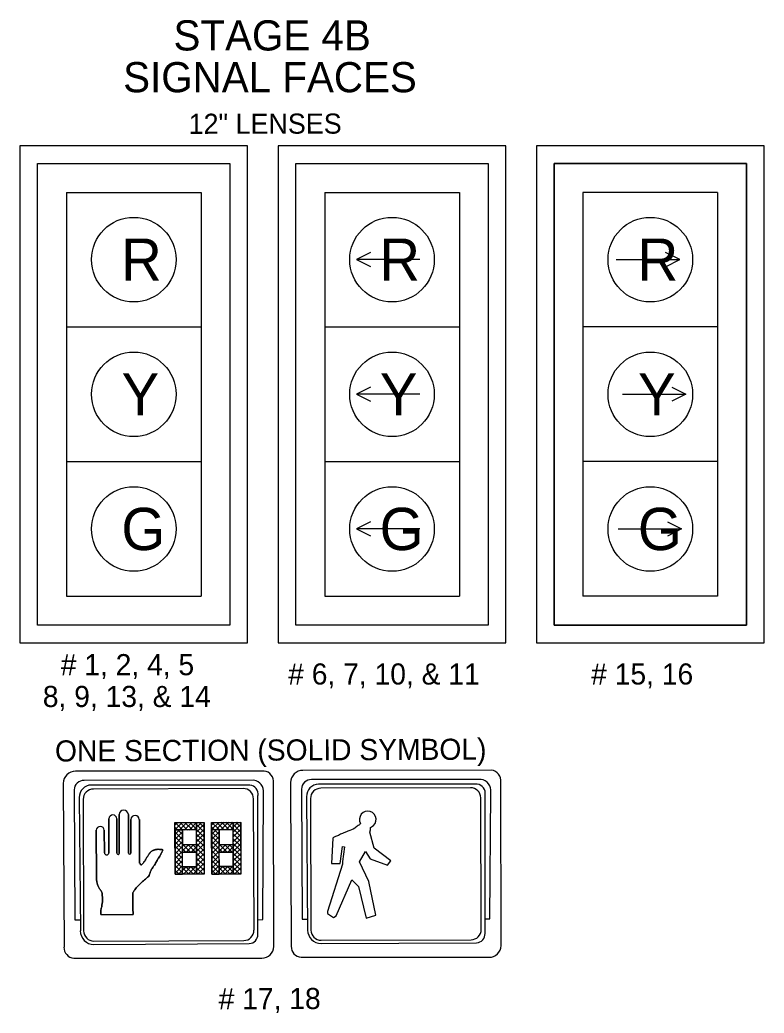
# Model space of a CAD drawing. Extents: x -218554 to 420030, y -565899 to -483460.
# Drawn here: x 418293.9 to 418442, y -565493.6 to -565296.1 of the extents above; entities that cross this region are included whole.
import ezdxf

# ---------------------------------------------------------------- set-up
doc = ezdxf.new("R2010")
doc.units = 0
for name, color, linetype in [('G-ANNO-STMP', 7, 'Continuous'), ('G-Border-Paper', 7, 'Continuous'), ('Level 1', 7, 'Continuous'), ('Level 61', 7, 'Continuous')]:
    doc.layers.add(name, color=color, linetype=linetype)

msp = doc.modelspace()

# ---------------------------------------------------------------- linework, layer by layer
at = {"layer": 'G-Border-Paper'}
for points in [[(418293.92, -565321.11), (418293.92, -565419.92), (418339.23, -565419.92), (418339.23, -565321.11), (418293.92, -565321.11)], [(418345.29, -565321.11), (418345.29, -565419.92), (418390.6, -565419.92), (418390.6, -565321.11), (418345.29, -565321.11)], [(418396.66, -565321.11), (418396.66, -565419.92), (418441.96, -565419.92), (418441.96, -565321.11), (418396.66, -565321.11)], [(418297.46, -565416.41), (418297.46, -565324.61), (418335.71, -565324.61), (418335.71, -565416.41), (418297.46, -565416.41)], [(418348.82, -565416.41), (418348.82, -565324.61), (418387.08, -565324.61), (418387.08, -565416.41), (418348.82, -565416.41)], [(418400.19, -565416.41), (418400.19, -565324.61), (418438.45, -565324.61), (418438.45, -565416.41), (418400.19, -565416.41)]]:
    msp.add_lwpolyline(points, dxfattribs=at)
at = {"layer": 'Level 1'}
for p, q in [((418342.52, -565445.42), (418305.02, -565445.45)), ((418387.72, -565445.26), (418350.22, -565445.29)), ((418302.57, -565447.88), (418302.71, -565480.42)), ((418340.45, -565447.24), (418306.73, -565447.28)), ((418339.68, -565448.2), (418308.13, -565448.2)), ((418344.42, -565480.3), (418344.39, -565447.79)), ((418347.77, -565447.72), (418347.91, -565480.26)), ((418385.66, -565447.08), (418351.94, -565447.12)), ((418384.89, -565448.04), (418353.34, -565448.05)), ((418389.63, -565480.14), (418389.59, -565447.63)), ((418386.46, -565477.72), (418386.5, -565450.16)), ((418305.73, -565450.68), (418305.96, -565477.2)), ((418341.26, -565477.88), (418341.29, -565450.31)), ((418350.94, -565450.52), (418351.16, -565477.04)), ((418313.7, -565461.8), (418313.67, -565454.08)), ((418313.67, -565454.08), (418313.7, -565461.8)), ((418315.51, -565454.05), (418315.54, -565461.72)), ((418315.54, -565461.72), (418315.51, -565454.05)), ((418311.64, -565461.66), (418311.62, -565454.91)), ((418311.62, -565454.91), (418311.64, -565461.66)), ((418313.22, -565454.92), (418313.24, -565461.76)), ((418313.24, -565461.76), (418313.22, -565454.92)), ((418316, -565461.75), (418315.97, -565455.03)), ((418315.97, -565455.03), (418316, -565461.75)), ((418317.69, -565455.07), (418317.72, -565463.73)), ((418317.72, -565463.73), (418317.69, -565455.07)), ((418324.77, -565456.14), (418325.25, -565455.65)), ((418324.78, -565457.09), (418326.21, -565455.65)), ((418324.78, -565458.05), (418327.16, -565455.65)), ((418324.83, -565455.66), (418326.33, -565457.15)), ((418325.79, -565455.65), (418327.29, -565457.15)), ((418326.63, -565457.15), (418328.12, -565455.64)), ((418326.74, -565455.65), (418328.25, -565457.14)), ((418327.58, -565457.15), (418329.08, -565455.64)), ((418327.7, -565455.65), (418330.55, -565458.48)), ((418328.54, -565457.14), (418330.03, -565455.64)), ((418328.66, -565455.64), (418330.55, -565457.52)), ((418329.05, -565457.59), (418330.54, -565456.08)), ((418329.61, -565455.64), (418330.55, -565456.57)), ((418332.07, -565458.02), (418334.46, -565455.62)), ((418332.07, -565456.11), (418332.55, -565455.63)), ((418332.07, -565457.07), (418333.5, -565455.63)), ((418332.12, -565455.63), (418333.63, -565457.13)), ((418333.08, -565455.63), (418334.59, -565457.12)), ((418333.92, -565457.12), (418335.42, -565455.62)), ((418334.04, -565455.62), (418335.54, -565457.12)), ((418334.88, -565457.12), (418336.37, -565455.62)), ((418334.99, -565455.62), (418337.85, -565458.45)), ((418335.83, -565457.12), (418337.33, -565455.61)), ((418335.95, -565455.62), (418337.84, -565457.5)), ((418336.34, -565457.56), (418337.84, -565456.06)), ((418336.91, -565455.61), (418337.84, -565456.54)), ((418309.16, -565466.52), (418309.13, -565457.2)), ((418309.13, -565457.2), (418309.16, -565466.52)), ((418310.72, -565457.21), (418310.74, -565461.66)), ((418310.74, -565461.66), (418310.72, -565457.21)), ((418324.77, -565456.55), (418326.28, -565458.05)), ((418324.78, -565459.01), (418326.28, -565457.5)), ((418324.78, -565457.51), (418326.28, -565459.01)), ((418329.05, -565458.55), (418330.55, -565457.04)), ((418329.05, -565457.94), (418330.56, -565459.44)), ((418329.06, -565459.5), (418330.55, -565458)), ((418332.07, -565456.53), (418333.57, -565458.02)), ((418332.07, -565457.49), (418333.58, -565458.98)), ((418332.08, -565458.98), (418333.57, -565457.48)), ((418336.35, -565458.52), (418337.84, -565457.02)), ((418336.35, -565457.92), (418337.85, -565459.41)), ((418336.35, -565459.48), (418337.85, -565457.97)), ((418363.87, -565456.54), (418363.87, -565456.54)), ((418324.78, -565458.47), (418327.88, -565461.55)), ((418324.78, -565459.43), (418326.92, -565461.55)), ((418324.79, -565459.96), (418326.28, -565458.46)), ((418324.79, -565460.92), (418326.28, -565459.41)), ((418324.79, -565461.88), (418326.61, -565460.05)), ((418324.8, -565462.83), (418327.56, -565460.05)), ((418326.29, -565460.05), (418329.06, -565460.04)), ((418327.02, -565461.55), (418328.52, -565460.04)), ((418327.33, -565460.05), (418328.84, -565461.54)), ((418327.98, -565461.54), (418330.55, -565458.95)), ((418328.29, -565460.04), (418330.57, -565462.31)), ((418328.94, -565461.54), (418330.56, -565459.91)), ((418329.05, -565458.9), (418330.56, -565460.39)), ((418329.06, -565459.85), (418330.56, -565461.35)), ((418332.08, -565459.94), (418333.58, -565458.43)), ((418332.08, -565458.44), (418335.17, -565461.52)), ((418332.08, -565460.89), (418333.58, -565459.39)), ((418332.08, -565459.4), (418334.22, -565461.52)), ((418332.09, -565461.85), (418333.9, -565460.02)), ((418332.09, -565462.81), (418334.86, -565460.02)), ((418333.58, -565460.03), (418336.35, -565460.02)), ((418334.32, -565461.52), (418335.81, -565460.02)), ((418334.63, -565460.02), (418336.13, -565461.52)), ((418335.28, -565461.52), (418337.85, -565458.93)), ((418335.58, -565460.02), (418337.86, -565462.28)), ((418336.23, -565461.52), (418337.85, -565459.89)), ((418336.35, -565458.87), (418337.85, -565460.37)), ((418336.35, -565459.83), (418337.86, -565461.32)), ((418324.79, -565460.38), (418326.29, -565461.88)), ((418324.79, -565461.34), (418326.3, -565462.83)), ((418326.29, -565461.55), (418329.06, -565461.54)), ((418329.06, -565461.77), (418330.57, -565463.26)), ((418329.07, -565462.37), (418330.56, -565460.87)), ((418329.07, -565463.33), (418330.56, -565461.82)), ((418332.08, -565460.36), (418333.59, -565461.85)), ((418332.09, -565461.31), (418333.59, -565462.81)), ((418333.59, -565461.53), (418336.36, -565461.52)), ((418336.36, -565462.35), (418337.86, -565460.84)), ((418336.36, -565461.74), (418337.86, -565463.24)), ((418336.36, -565463.3), (418337.86, -565461.8)), ((418324.79, -565462.3), (418326.3, -565463.79)), ((418324.8, -565463.79), (418326.29, -565462.28)), ((418324.8, -565464.75), (418326.3, -565463.24)), ((418324.8, -565463.25), (418327.51, -565465.95)), ((418327.42, -565465.95), (418330.57, -565462.78)), ((418328.38, -565465.94), (418330.57, -565463.74)), ((418329.07, -565462.73), (418330.57, -565464.22)), ((418329.07, -565463.68), (418330.58, -565465.18)), ((418332.09, -565463.76), (418333.59, -565462.26)), ((418332.09, -565462.27), (418333.59, -565463.76)), ((418332.09, -565463.23), (418334.81, -565465.92)), ((418332.1, -565464.72), (418333.59, -565463.22)), ((418334.72, -565465.92), (418337.86, -565462.76)), ((418335.68, -565465.92), (418337.87, -565463.71)), ((418336.36, -565462.7), (418337.87, -565464.19)), ((418336.37, -565463.66), (418337.87, -565465.15)), ((418324.8, -565464.21), (418326.55, -565465.95)), ((418324.8, -565465.17), (418325.6, -565465.95)), ((418324.81, -565465.7), (418326.3, -565464.2)), ((418325.51, -565465.95), (418327, -565464.45)), ((418326.47, -565465.95), (418327.96, -565464.44)), ((418326.96, -565464.45), (418328.47, -565465.94)), ((418327.92, -565464.45), (418329.42, -565465.94)), ((418328.88, -565464.44), (418330.38, -565465.94)), ((418329.34, -565465.94), (418330.57, -565464.69)), ((418330.29, -565465.94), (418330.58, -565465.65)), ((418332.1, -565465.68), (418333.6, -565464.17)), ((418332.1, -565464.18), (418333.85, -565465.92)), ((418332.1, -565465.14), (418332.89, -565465.93)), ((418332.8, -565465.93), (418334.3, -565464.42)), ((418333.76, -565465.92), (418335.26, -565464.42)), ((418334.26, -565464.42), (418335.76, -565465.92)), ((418335.21, -565464.42), (418336.72, -565465.91)), ((418336.17, -565464.42), (418337.68, -565465.91)), ((418336.63, -565465.91), (418337.87, -565464.67)), ((418337.59, -565465.91), (418337.87, -565465.63)), ((418310.02, -565473.96), (418316.46, -565473.98)), ((418316.44, -565473.98), (418310.06, -565474)), ((418316.47, -565473.98), (418316.44, -565473.98)), ((418308.66, -565479.89), (418339.56, -565479.72)), ((418353.87, -565479.73), (418384.76, -565479.57)), ((418304.68, -565482.61), (418342.02, -565482.61)), ((418349.88, -565482.46), (418387.23, -565482.46))]:
    msp.add_line(p, q, dxfattribs=at)
for points in [[(418304.72, -565449.17), (418304.89, -565475.03), (418305.97, -565475.02)], [(418338.36, -565448.89), (418308.56, -565449)], [(418341.24, -565474.98), (418342.22, -565474.97), (418342.38, -565449.79)], [(418349.93, -565449.02), (418350.09, -565474.87), (418351.18, -565474.87)], [(418383.56, -565448.74), (418353.76, -565448.84)], [(418386.45, -565474.82), (418387.42, -565474.81), (418387.58, -565449.63)], [(418306.52, -565451.05), (418306.61, -565477.2)], [(418340.5, -565477.08), (418340.41, -565450.93)], [(418351.72, -565450.89), (418351.81, -565477.04)], [(418385.7, -565476.92), (418385.61, -565450.77)], [(418329.06, -565460.04), (418329.05, -565457.14), (418326.28, -565457.15), (418326.29, -565460.05)], [(418336.35, -565460.02), (418336.34, -565457.12), (418333.57, -565457.13), (418333.58, -565460.03)], [(418356.2, -565458.74), (418355.92, -565463.81), (418357.66, -565463.81), (418358.1, -565460.45), (418358.5, -565460.46), (418358.07, -565463.44), (418358.07, -565463.94), (418355.12, -565473.36), (418355.13, -565473.73), (418356.32, -565474.55), (418356.82, -565474.18), (418359.96, -565467.06), (418361.25, -565468.38), (418362.78, -565474.66), (418364.75, -565474.06), (418363.36, -565467.41), (418361.46, -565463.47), (418362.69, -565461.45), (418363.57, -565462.91), (418367.06, -565464.14), (418367.74, -565463.27), (418364.42, -565460.77), (418363.55, -565457.6), (418363.69, -565457.13), (418363.69, -565456.62), (418363.87, -565456.54)], [(418329.06, -565461.54), (418329.07, -565464.44), (418326.3, -565464.45), (418326.29, -565461.55)], [(418336.36, -565461.52), (418336.37, -565464.42), (418333.6, -565464.43), (418333.59, -565461.53)], [(418308.66, -565479.23), (418338.46, -565479.13)], [(418353.87, -565479.08), (418383.67, -565478.97)]]:
    msp.add_lwpolyline(points, dxfattribs=at)
for points in [[(418324.77, -565455.66), (418330.54, -565455.64), (418330.58, -565465.94), (418324.81, -565465.96)], [(418324.77, -565455.66), (418329.05, -565455.65), (418329.05, -565457.14), (418324.77, -565457.14)], [(418329.05, -565455.65), (418330.57, -565455.65), (418330.58, -565465.94), (418329.05, -565465.94)], [(418332.07, -565455.63), (418337.84, -565455.61), (418337.87, -565465.91), (418332.1, -565465.93)], [(418332.07, -565455.63), (418336.34, -565455.63), (418336.34, -565457.12), (418332.07, -565457.12)], [(418336.34, -565455.63), (418337.86, -565455.63), (418337.87, -565465.91), (418336.35, -565465.91)], [(418324.81, -565465.96), (418326.28, -565465.95), (418326.28, -565457.15), (418324.8, -565457.15)], [(418332.1, -565465.93), (418333.58, -565465.93), (418333.57, -565457.13), (418332.09, -565457.13)], [(418326.29, -565460.05), (418329.06, -565460.05), (418329.06, -565461.54), (418326.29, -565461.54)], [(418333.58, -565460.03), (418336.36, -565460.02), (418336.36, -565461.52), (418333.58, -565461.52)], [(418326.3, -565464.45), (418329.05, -565464.45), (418329.05, -565465.94), (418326.3, -565465.94)], [(418333.6, -565464.43), (418336.35, -565464.42), (418336.35, -565465.91), (418333.6, -565465.91)]]:
    msp.add_lwpolyline(points, close=True, dxfattribs=at)
for centre, radius, start, end in [((418305.01, -565447.89), 2.44, 89.8211, 179.8211), ((418342.26, -565447.54), 2.14, 353.227, 83.227), ((418350.22, -565447.73), 2.44, 89.8211, 179.8211), ((418387.47, -565447.38), 2.14, 353.227, 83.227), ((418306.67, -565449.23), 1.95, 88.3219, 178.3219), ((418308.17, -565450.64), 2.44, 90.9287, 180.9287), ((418339.43, -565450.06), 1.88, 352.2729, 82.2729), ((418340.14, -565449.48), 2.26, 351.9574, 81.9574), ((418351.88, -565449.07), 1.95, 88.3219, 178.3219), ((418353.38, -565450.48), 2.44, 90.9287, 180.9287), ((418384.63, -565449.9), 1.88, 352.2729, 82.2729), ((418385.34, -565449.32), 2.26, 351.9574, 81.9574), ((418308.56, -565451.04), 2.04, 90.1989, 180.1989), ((418338.36, -565450.94), 2.04, 0.1989, 90.1989), ((418353.77, -565450.88), 2.04, 90.1989, 180.1989), ((418383.57, -565450.78), 2.04, 0.1989, 90.1989), ((418314.59, -565454.12), 0.921, 4.0989, 177.4457), ((418314.59, -565454.12), 0.921, 4.0989, 177.4457), ((418363.12, -565455.05), 1.66, 296.6638, 209.0011), ((418312.42, -565454.96), 0.801, 2.8665, 176.2133), ((418312.42, -565454.96), 0.801, 2.8665, 176.2133), ((418316.83, -565455.1), 0.857, 1.6765, 175.0233), ((418316.83, -565455.1), 0.857, 1.6765, 175.0233), ((418309.92, -565457.25), 0.801, 2.8665, 176.2133), ((418309.92, -565457.25), 0.801, 2.8665, 176.2133), ((418311.19, -565461.66), 0.45, 180.1989, 0.1989), ((418311.19, -565461.66), 0.45, 180.1989, 0.1989), ((418313.47, -565461.78), 0.231, 175.6215, 355.6215), ((418313.47, -565461.78), 0.231, 175.6215, 355.6215), ((418315.76, -565461.73), 0.234, 175.0942, 355.0942), ((418315.76, -565461.73), 0.234, 175.0942, 355.0942), ((418308.65, -565477.19), 2.7, 180.1989, 270.1989), ((418308.65, -565477.19), 2.04, 180.1989, 270.1989), ((418338.45, -565477.08), 2.04, 270.1989, 0.1989), ((418353.86, -565477.03), 2.7, 180.1989, 270.1989), ((418353.86, -565477.03), 2.04, 180.1989, 270.1989), ((418383.66, -565476.93), 2.04, 270.1989, 0.1989), ((418384.69, -565477.79), 1.77, 272.3085, 2.3085), ((418339.49, -565477.95), 1.77, 272.3085, 2.3085), ((418304.79, -565480.53), 2.09, 176.9799, 266.9799), ((418342.07, -565480.26), 2.36, 268.9594, 358.9594), ((418350, -565480.37), 2.09, 176.9799, 266.9799), ((418387.27, -565480.1), 2.36, 268.9594, 358.9594)]:
    msp.add_arc(centre, radius, start, end, dxfattribs=at)
for points in [[(418361.66, -565455.86), (418361.47, -565456.13), (418361.21, -565456.27), (418360.89, -565456.5), (418360.53, -565456.77), (418359.19, -565457.38), (418358.55, -565457.66), (418357.93, -565457.9), (418357.09, -565458.3), (418356.69, -565458.45), (418356.2, -565458.74)], [(418317.71, -565463.73), (418317.77, -565463.74), (418317.86, -565463.92), (418317.97, -565464.05), (418318.04, -565464.07), (418318.15, -565464.05), (418318.22, -565463.96), (418318.42, -565463.74), (418318.57, -565463.56), (418318.66, -565463.43), (418318.75, -565463.32), (418318.9, -565463.12), (418318.99, -565462.94), (418319.12, -565462.7), (418319.21, -565462.57), (418319.36, -565462.32), (418319.54, -565462.1), (418319.67, -565461.88), (418319.82, -565461.66), (418319.95, -565461.5), (418320.15, -565461.33), (418320.4, -565461.23), (418320.53, -565461.17), (418320.73, -565461.1), (418320.9, -565461.04), (418321.17, -565460.99), (418321.39, -565460.99), (418321.68, -565460.99), (418321.94, -565461.01), (418322.25, -565461.05), (418322.34, -565461.1), (418322.36, -565461.16), (418322.23, -565461.45), (418322.14, -565461.6), (418322.06, -565461.76), (418321.97, -565461.94), (418321.92, -565462.05), (418321.75, -565462.34), (418321.48, -565462.74), (418321.13, -565463.38), (418320.69, -565464.11), (418320.34, -565464.62), (418320.14, -565464.95), (418319.97, -565465.26), (418319.87, -565465.51), (418319.81, -565465.64), (418319.62, -565466.17), (418319.31, -565466.55), (418319.07, -565466.81), (418318.71, -565467.08), (418318.49, -565467.24), (418317.92, -565467.81), (418317.41, -565468.3), (418317.08, -565468.63), (418316.8, -565469.01), (418316.66, -565469.18), (418316.54, -565469.41), (418316.4, -565469.63), (418316.41, -565470.12), (418316.38, -565470.56), (418316.39, -565470.96), (418316.41, -565471.49), (418316.41, -565471.99), (418316.41, -565472.81), (418316.44, -565473.47), (418316.46, -565473.71), (418316.46, -565473.89), (418316.46, -565473.98)], [(418316.46, -565473.98), (418316.46, -565473.89), (418316.46, -565473.71), (418316.44, -565473.47), (418316.41, -565472.81), (418316.41, -565471.99), (418316.41, -565471.49), (418316.39, -565470.96), (418316.38, -565470.56), (418316.41, -565470.12), (418316.4, -565469.63), (418316.54, -565469.41), (418316.66, -565469.18), (418316.8, -565469.01), (418317.08, -565468.63), (418317.41, -565468.3), (418317.92, -565467.81), (418318.49, -565467.24), (418318.71, -565467.08), (418319.07, -565466.81), (418319.31, -565466.55), (418319.62, -565466.17), (418319.81, -565465.64), (418319.87, -565465.51), (418319.97, -565465.26), (418320.14, -565464.95), (418320.34, -565464.62), (418320.69, -565464.11), (418321.13, -565463.38), (418321.48, -565462.74), (418321.75, -565462.34), (418321.92, -565462.05), (418321.97, -565461.94), (418322.06, -565461.76), (418322.14, -565461.6), (418322.23, -565461.45), (418322.36, -565461.16), (418322.34, -565461.1), (418322.25, -565461.05), (418321.94, -565461.01), (418321.68, -565460.99), (418321.39, -565460.99), (418321.17, -565460.99), (418320.9, -565461.04), (418320.73, -565461.1), (418320.53, -565461.17), (418320.4, -565461.23), (418320.15, -565461.33), (418319.95, -565461.5), (418319.82, -565461.66), (418319.67, -565461.88), (418319.54, -565462.1), (418319.36, -565462.32), (418319.21, -565462.57), (418319.12, -565462.7), (418318.99, -565462.94), (418318.9, -565463.12), (418318.75, -565463.32), (418318.66, -565463.43), (418318.57, -565463.56), (418318.42, -565463.74), (418318.22, -565463.96), (418318.15, -565464.05), (418318.04, -565464.07), (418317.97, -565464.05), (418317.86, -565463.92), (418317.77, -565463.74), (418317.71, -565463.73)], [(418310.02, -565473.96), (418310.02, -565473.61), (418310.04, -565473.01), (418310.21, -565472.39), (418310.3, -565471.68), (418310.37, -565471.28), (418310.36, -565470.51), (418310.29, -565469.87), (418310.23, -565469.54), (418309.89, -565468.98), (418309.54, -565468.43), (418309.34, -565467.97), (418309.25, -565467.48), (418309.18, -565467.11), (418309.18, -565466.87), (418309.16, -565466.52)], [(418309.16, -565466.52), (418309.18, -565466.87), (418309.18, -565467.11), (418309.25, -565467.48), (418309.34, -565467.97), (418309.54, -565468.43), (418309.89, -565468.98), (418310.23, -565469.54), (418310.29, -565469.87), (418310.36, -565470.51), (418310.37, -565471.28), (418310.3, -565471.68), (418310.21, -565472.39), (418310.04, -565473.01), (418310.02, -565473.61), (418310.02, -565473.96)]]:
    msp.add_spline(points, degree=3, dxfattribs=at)
at = {"layer": 'Level 61'}
for p, q in [((418303.19, -565330.35), (418329.97, -565330.35)), ((418303.19, -565330.35), (418303.19, -565357.12)), ((418329.97, -565330.35), (418329.97, -565357.12)), ((418354.56, -565330.35), (418381.34, -565330.35)), ((418354.56, -565330.35), (418354.56, -565357.12)), ((418381.34, -565330.35), (418381.34, -565357.12)), ((418432.71, -565330.35), (418405.93, -565330.35)), ((418405.93, -565330.35), (418405.93, -565357.12)), ((418432.71, -565330.35), (418432.71, -565357.12)), ((418373.5, -565343.7), (418360.88, -565343.7)), ((418412.55, -565343.73), (418425.17, -565343.73)), ((418303.19, -565357.12), (418329.97, -565357.12)), ((418303.19, -565357.12), (418303.19, -565383.9)), ((418329.97, -565357.12), (418329.97, -565383.9)), ((418354.56, -565357.12), (418381.34, -565357.12)), ((418354.56, -565357.12), (418354.56, -565383.9)), ((418381.34, -565357.12), (418381.34, -565383.9)), ((418432.71, -565357.12), (418405.93, -565357.12)), ((418405.93, -565357.12), (418405.93, -565383.9)), ((418432.71, -565357.12), (418432.71, -565383.9)), ((418373.5, -565370.47), (418360.88, -565370.47)), ((418413.77, -565370.47), (418426.39, -565370.47)), ((418303.19, -565383.9), (418329.97, -565383.9)), ((418303.19, -565383.9), (418303.19, -565410.68)), ((418329.97, -565383.9), (418329.97, -565410.68)), ((418354.56, -565383.9), (418381.34, -565383.9)), ((418354.56, -565383.9), (418354.56, -565410.68)), ((418381.34, -565383.9), (418381.34, -565410.68)), ((418432.71, -565383.9), (418405.93, -565383.9)), ((418405.93, -565383.9), (418405.93, -565410.68)), ((418432.71, -565383.9), (418432.71, -565410.68)), ((418373.5, -565397.25), (418360.88, -565397.25)), ((418412.91, -565397.29), (418425.53, -565397.29)), ((418303.19, -565410.68), (418329.97, -565410.68)), ((418354.56, -565410.68), (418381.34, -565410.68)), ((418432.71, -565410.68), (418405.93, -565410.68))]:
    msp.add_line(p, q, dxfattribs=at)
for points in [[(418297.46, -565324.61), (418335.71, -565324.61), (418335.71, -565416.41), (418297.46, -565416.41)], [(418348.82, -565324.61), (418387.08, -565324.61), (418387.08, -565416.41), (418348.82, -565416.41)], [(418438.45, -565324.61), (418400.19, -565324.61), (418400.19, -565416.41), (418438.45, -565416.41)]]:
    msp.add_lwpolyline(points, close=True, dxfattribs=at)
for points in [[(418363.68, -565342.3), (418360.88, -565343.7), (418363.68, -565345.1)], [(418422.37, -565345.14), (418425.17, -565343.73), (418422.37, -565342.33)], [(418363.68, -565369.07), (418360.88, -565370.47), (418363.68, -565371.88)], [(418423.59, -565369.07), (418426.39, -565370.47), (418423.59, -565371.88)], [(418363.68, -565395.85), (418360.88, -565397.25), (418363.68, -565398.65)], [(418422.73, -565395.88), (418425.53, -565397.29), (418422.73, -565398.69)]]:
    msp.add_lwpolyline(points, dxfattribs=at)
for centre in [(418316.58, -565343.73), (418367.95, -565343.73), (418419.32, -565343.73), (418316.58, -565370.51), (418367.95, -565370.51), (418419.32, -565370.51), (418316.58, -565397.29), (418367.95, -565397.29), (418419.32, -565397.29)]:
    msp.add_circle(centre, 8.41, dxfattribs=at)

# ---------------------------------------------------------------- texts
at = {"layer": 'G-ANNO-STMP'}
for s, p in [('# 1, 2, 4, 5', (418302.05, -565426.37)), ('# 6, 7, 10, & 11', (418347.3, -565428.22)), ('# 15, 16', (418407.56, -565428.22)), ('8, 9, 13, & 14', (418298.49, -565432.69))]:
    msp.add_text(s, height=4.2, dxfattribs=at).set_placement(p)
for s, p in [('ONE SECTION (SOLID SYMBOL)', (418300.92, -565443.53)), ('# 17, 18', (418333.47, -565492.83))]:
    msp.add_text(s, height=4.2, rotation=0.2455, dxfattribs=at).set_placement(p)
at = {"layer": 'Level 61'}
for s, height, p in [('STAGE 4B', 6, (418324.49, -565302.14)), ('SIGNAL FACES', 6, (418314.47, -565310.45)), ('R', 8.41, (418314.04, -565347.94)), ('R', 8.41, (418365.41, -565347.94)), ('R', 8.41, (418416.78, -565347.94)), ('Y', 8.41, (418314.14, -565374.72)), ('Y', 8.41, (418365.51, -565374.72)), ('Y', 8.41, (418416.87, -565374.72)), ('G', 8.41, (418314.11, -565401.49)), ('G', 8.41, (418365.48, -565401.49)), ('G', 8.41, (418416.85, -565401.49))]:
    msp.add_text(s, height=height, dxfattribs=at).set_placement(p)
msp.add_text('12" LENSES', height=4, rotation=0.072, dxfattribs=at).set_placement((418327.49, -565318.72))

doc.saveas('drawing.dxf')
